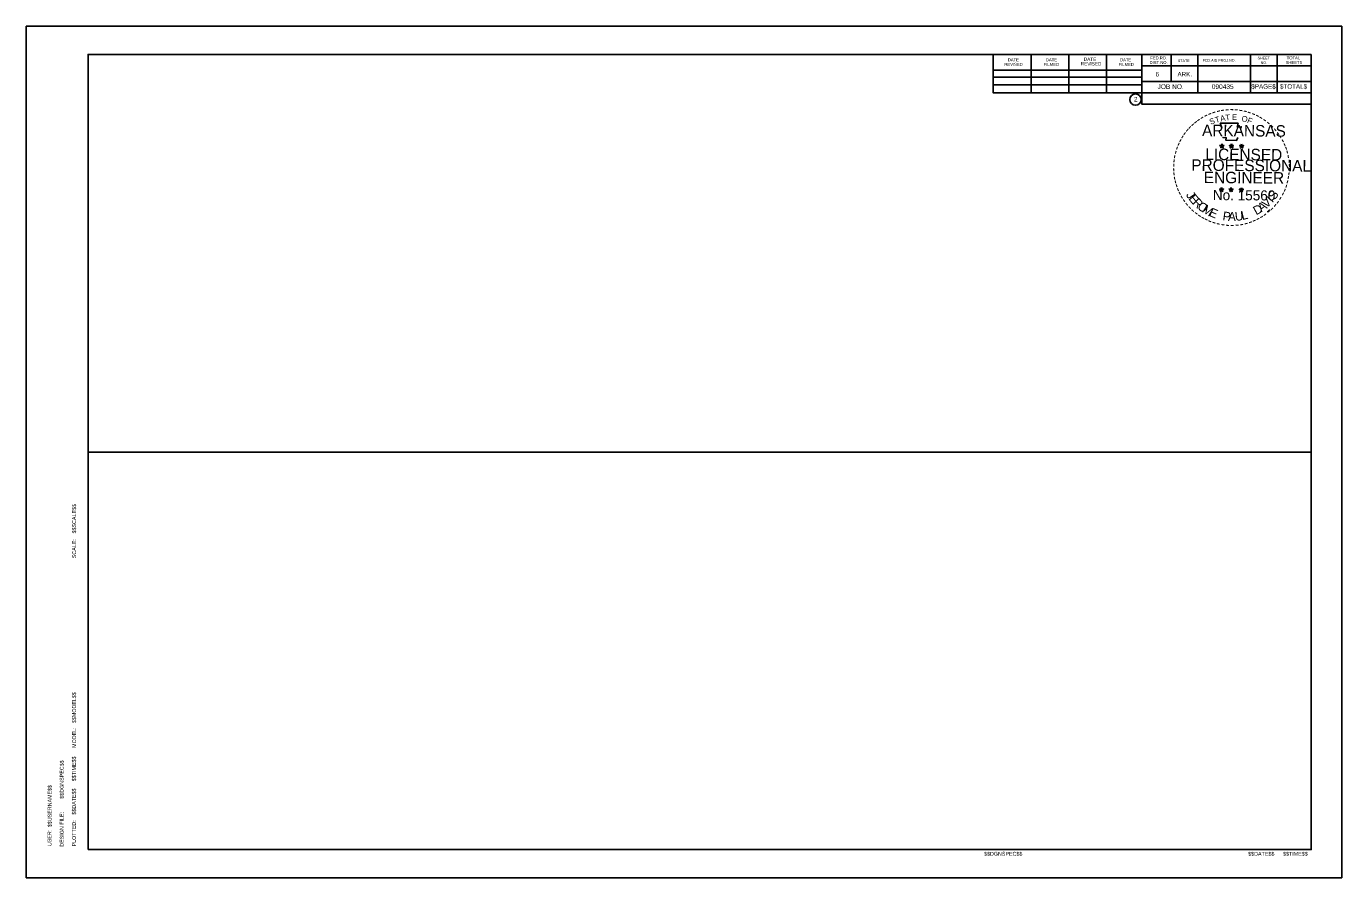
# Model space of a CAD drawing. Extents: x -1.6 to 32.4, y -0.7 to 21.3.
import ezdxf

# ---------------------------------------------------------------- set-up
doc = ezdxf.new("R2010")
doc.units = 0
for name, color, linetype in [('Level 1', 7, 'Continuous'), ('Level 24', 7, 'Continuous'), ('Level 37', 7, 'Continuous'), ('Level 48', 7, 'Continuous'), ('Level 49', 7, 'Continuous'), ('Level 62', 7, 'Continuous'), ('Level 63', 7, 'Continuous')]:
    doc.layers.add(name, color=color, linetype=linetype)

msp = doc.modelspace()

# ---------------------------------------------------------------- linework, layer by layer
at = {"layer": 'Level 1'}
for p, q in [((-0.001, 20.545), (31.617, 20.545)), ((-0.001, -0.001), (-0.001, 20.545)), ((23.391, 19.557), (23.391, 20.545)), ((24.377, 19.557), (24.377, 20.525)), ((25.353, 19.557), (25.353, 20.525)), ((26.321, 19.557), (26.321, 20.525)), ((27.233, 20.545), (27.233, 19.557)), ((27.991, 20.545), (27.991, 19.851)), ((28.685, 20.545), (28.685, 19.557)), ((30.043, 20.545), (30.043, 19.557)), ((30.737, 20.545), (30.737, 19.557)), ((31.617, -0.001), (31.617, 20.545)), ((23.391, 20.143), (27.233, 20.143)), ((31.617, 20.251), (27.233, 20.251)), ((31.617, 20.253), (31.617, 20.253)), ((23.391, 19.957), (27.233, 19.957)), ((23.391, 19.557), (23.391, 19.763)), ((23.391, 19.763), (27.233, 19.763)), ((31.617, 19.851), (27.233, 19.851)), ((27.603, 19.851), (31.617, 19.851)), ((31.617, 19.557), (23.391, 19.557)), ((27.233, 19.557), (27.233, 19.265)), ((27.233, 19.265), (31.617, 19.265)), ((31.617, -0.001), (-0.001, -0.001))]:
    msp.add_line(p, q, dxfattribs=at)
msp.add_circle((27.073, 19.379), 0.147, dxfattribs=at)
at = {"layer": 'Level 24'}
for p, q in [((-0.001, 20.545), (-0.001, -0.001)), ((23.391, 19.557), (23.391, 20.545)), ((26.999, 19.557), (23.391, 19.557)), ((27.233, 19.557), (26.999, 19.557)), ((27.233, 19.265), (27.233, 19.557)), ((27.233, 19.557), (27.233, 19.557)), ((31.617, 19.265), (27.233, 19.265)), ((31.617, -0.001), (31.617, 19.265)), ((-0.001, -0.001), (31.617, -0.001))]:
    msp.add_line(p, q, dxfattribs=at)
msp.add_lwpolyline([(23.391, 20.545), (23.391, 20.545), (23.391, 20.545), (-0.001, 20.545)], dxfattribs=at)
at = {"layer": 'Level 37'}
for p, q in [((-0.002, 10.755), (-0.001, 20.545)), ((-0.001, 20.545), (31.617, 20.545)), ((31.617, 20.545), (31.617, 10.273)), ((-0.001, 10.273), (-0.002, 10.755)), ((-0.002, 10.755), (-0.002, 10.755)), ((-0.002, 0.481), (-0.001, 10.271)), ((-0.002, 0.481), (-0.001, 10.271)), ((31.617, 10.273), (-0.001, 10.273)), ((-0.001, 10.271), (31.617, 10.271)), ((-0.001, 10.271), (31.617, 10.271)), ((31.617, 10.271), (31.617, -0.001)), ((31.617, 10.271), (31.617, -0.001)), ((-0.001, -0.001), (-0.002, 0.481)), ((-0.002, 0.481), (-0.002, 0.481)), ((-0.001, -0.001), (-0.002, 0.481)), ((-0.002, 0.481), (-0.002, 0.481)), ((31.617, -0.001), (-0.001, -0.001)), ((31.617, -0.001), (-0.001, -0.001))]:
    msp.add_line(p, q, dxfattribs=at)
at = {"layer": 'Level 49'}
for p, q in [((29.252, 18.195), (29.306, 18.178)), ((29.252, 18.195), (29.291, 18.193)), ((29.252, 18.195), (29.291, 18.191)), ((29.252, 18.195), (29.287, 18.186)), ((29.252, 18.195), (29.287, 18.18)), ((29.252, 18.195), (29.287, 18.178)), ((29.252, 18.195), (29.287, 18.173)), ((29.274, 18.134), (29.306, 18.178)), ((29.274, 18.134), (29.287, 18.176)), ((29.274, 18.134), (29.291, 18.171)), ((29.274, 18.134), (29.293, 18.169)), ((29.274, 18.134), (29.298, 18.165)), ((29.274, 18.134), (29.306, 18.165)), ((29.274, 18.134), (29.306, 18.162)), ((29.306, 18.235), (29.298, 18.195)), ((29.306, 18.235), (29.298, 18.199)), ((29.306, 18.235), (29.302, 18.199)), ((29.306, 18.178), (29.306, 18.235)), ((29.306, 18.235), (29.315, 18.195)), ((29.306, 18.235), (29.313, 18.199)), ((29.306, 18.235), (29.307, 18.199)), ((29.357, 18.195), (29.306, 18.178)), ((29.337, 18.132), (29.306, 18.178)), ((29.337, 18.132), (29.306, 18.165)), ((29.337, 18.132), (29.306, 18.162)), ((29.357, 18.195), (29.309, 18.191)), ((29.337, 18.132), (29.309, 18.165)), ((29.357, 18.195), (29.315, 18.188)), ((29.357, 18.195), (29.315, 18.184)), ((29.337, 18.132), (29.315, 18.176)), ((29.337, 18.132), (29.315, 18.171)), ((29.337, 18.132), (29.32, 18.178)), ((29.357, 18.195), (29.322, 18.184)), ((29.357, 18.195), (29.328, 18.18)), ((29.357, 18.195), (29.329, 18.178)), ((29.5, 18.193), (29.553, 18.178)), ((29.5, 18.193), (29.539, 18.191)), ((29.5, 18.193), (29.539, 18.188)), ((29.5, 18.193), (29.539, 18.186)), ((29.5, 18.193), (29.537, 18.178)), ((29.5, 18.193), (29.537, 18.176)), ((29.5, 18.193), (29.537, 18.171)), ((29.522, 18.132), (29.553, 18.178)), ((29.522, 18.132), (29.539, 18.173)), ((29.522, 18.132), (29.539, 18.171)), ((29.522, 18.132), (29.541, 18.169)), ((29.522, 18.132), (29.546, 18.164)), ((29.522, 18.132), (29.553, 18.164)), ((29.522, 18.132), (29.553, 18.162)), ((29.553, 18.232), (29.546, 18.193)), ((29.553, 18.232), (29.546, 18.195)), ((29.553, 18.232), (29.548, 18.195)), ((29.553, 18.178), (29.553, 18.232)), ((29.553, 18.232), (29.563, 18.193)), ((29.553, 18.232), (29.561, 18.195)), ((29.553, 18.232), (29.555, 18.195)), ((29.605, 18.193), (29.553, 18.178)), ((29.585, 18.132), (29.553, 18.178)), ((29.585, 18.132), (29.553, 18.164)), ((29.585, 18.132), (29.553, 18.162)), ((29.605, 18.193), (29.559, 18.191)), ((29.585, 18.132), (29.559, 18.164)), ((29.605, 18.193), (29.563, 18.186)), ((29.605, 18.193), (29.563, 18.184)), ((29.585, 18.132), (29.563, 18.176)), ((29.585, 18.132), (29.563, 18.169)), ((29.585, 18.132), (29.568, 18.176)), ((29.605, 18.193), (29.57, 18.18)), ((29.605, 18.193), (29.575, 18.178)), ((29.605, 18.193), (29.577, 18.176)), ((29.763, 18.191), (29.816, 18.173)), ((29.763, 18.191), (29.805, 18.186)), ((29.763, 18.191), (29.801, 18.184)), ((29.763, 18.191), (29.801, 18.18)), ((29.763, 18.191), (29.799, 18.176)), ((29.763, 18.191), (29.799, 18.171)), ((29.763, 18.191), (29.799, 18.171)), ((29.783, 18.131), (29.816, 18.173)), ((29.783, 18.131), (29.801, 18.171)), ((29.783, 18.131), (29.805, 18.165)), ((29.783, 18.131), (29.805, 18.164)), ((29.783, 18.131), (29.816, 18.164)), ((29.783, 18.131), (29.812, 18.162)), ((29.783, 18.131), (29.82, 18.156)), ((29.816, 18.228), (29.807, 18.193)), ((29.816, 18.228), (29.812, 18.191)), ((29.816, 18.228), (29.812, 18.191)), ((29.816, 18.173), (29.816, 18.228)), ((29.816, 18.228), (29.827, 18.191)), ((29.816, 18.228), (29.823, 18.191)), ((29.816, 18.228), (29.82, 18.191)), ((29.867, 18.191), (29.816, 18.173)), ((29.845, 18.131), (29.816, 18.173)), ((29.845, 18.131), (29.816, 18.164)), ((29.845, 18.131), (29.816, 18.156)), ((29.867, 18.191), (29.821, 18.186)), ((29.845, 18.131), (29.821, 18.162)), ((29.867, 18.191), (29.827, 18.184)), ((29.867, 18.191), (29.827, 18.178)), ((29.845, 18.131), (29.827, 18.171)), ((29.845, 18.131), (29.827, 18.165)), ((29.845, 18.131), (29.831, 18.171)), ((29.867, 18.191), (29.834, 18.176)), ((29.867, 18.191), (29.836, 18.176)), ((29.867, 18.191), (29.842, 18.173)), ((29.245, 17.068), (29.298, 17.051)), ((29.245, 17.068), (29.284, 17.066)), ((29.245, 17.068), (29.282, 17.06)), ((29.245, 17.068), (29.282, 17.06)), ((29.245, 17.068), (29.282, 17.053)), ((29.245, 17.068), (29.282, 17.051)), ((29.245, 17.068), (29.282, 17.049)), ((29.263, 17.011), (29.298, 17.051)), ((29.263, 17.011), (29.282, 17.051)), ((29.263, 17.011), (29.284, 17.044)), ((29.263, 17.011), (29.285, 17.044)), ((29.263, 17.011), (29.298, 17.042)), ((29.263, 17.011), (29.291, 17.038)), ((29.263, 17.011), (29.298, 17.037)), ((29.298, 17.108), (29.287, 17.071)), ((29.298, 17.108), (29.291, 17.068)), ((29.298, 17.108), (29.293, 17.068)), ((29.328, 17.007), (29.295, 17.037)), ((29.298, 17.051), (29.298, 17.108)), ((29.298, 17.108), (29.306, 17.068)), ((29.298, 17.108), (29.306, 17.068)), ((29.298, 17.108), (29.298, 17.068)), ((29.35, 17.068), (29.298, 17.051)), ((29.328, 17.007), (29.298, 17.051)), ((29.328, 17.007), (29.298, 17.038)), ((29.328, 17.007), (29.3, 17.038)), ((29.35, 17.068), (29.302, 17.066)), ((29.35, 17.068), (29.306, 17.06)), ((29.35, 17.068), (29.306, 17.059)), ((29.328, 17.007), (29.306, 17.051)), ((29.328, 17.007), (29.306, 17.044)), ((29.35, 17.068), (29.313, 17.057)), ((29.328, 17.007), (29.313, 17.051)), ((29.35, 17.068), (29.317, 17.053)), ((29.35, 17.068), (29.32, 17.051)), ((29.493, 17.068), (29.546, 17.051)), ((29.493, 17.068), (29.531, 17.064)), ((29.493, 17.068), (29.531, 17.06)), ((29.493, 17.068), (29.531, 17.059)), ((29.493, 17.068), (29.53, 17.053)), ((29.493, 17.068), (29.53, 17.049)), ((29.493, 17.068), (29.53, 17.046)), ((29.511, 17.007), (29.546, 17.051)), ((29.511, 17.007), (29.531, 17.049)), ((29.511, 17.007), (29.531, 17.042)), ((29.511, 17.007), (29.533, 17.042)), ((29.511, 17.007), (29.539, 17.038)), ((29.511, 17.007), (29.546, 17.038)), ((29.511, 17.007), (29.546, 17.035)), ((29.546, 17.104), (29.537, 17.068)), ((29.546, 17.104), (29.539, 17.068)), ((29.546, 17.104), (29.541, 17.068)), ((29.575, 17.007), (29.544, 17.035)), ((29.546, 17.051), (29.546, 17.104)), ((29.546, 17.104), (29.553, 17.066)), ((29.546, 17.104), (29.553, 17.066)), ((29.546, 17.104), (29.546, 17.068)), ((29.596, 17.066), (29.546, 17.051)), ((29.575, 17.007), (29.546, 17.051)), ((29.575, 17.007), (29.546, 17.038)), ((29.575, 17.007), (29.548, 17.038)), ((29.596, 17.066), (29.552, 17.066)), ((29.596, 17.066), (29.553, 17.059)), ((29.596, 17.066), (29.553, 17.059)), ((29.575, 17.007), (29.553, 17.049)), ((29.575, 17.007), (29.553, 17.044)), ((29.596, 17.066), (29.561, 17.053)), ((29.575, 17.007), (29.561, 17.049)), ((29.596, 17.066), (29.566, 17.051)), ((29.596, 17.066), (29.568, 17.049)), ((29.755, 17.064), (29.809, 17.046)), ((29.755, 17.064), (29.794, 17.06)), ((29.755, 17.064), (29.794, 17.057)), ((29.755, 17.064), (29.792, 17.053)), ((29.755, 17.064), (29.792, 17.049)), ((29.755, 17.064), (29.79, 17.046)), ((29.755, 17.064), (29.79, 17.042)), ((29.775, 17.003), (29.809, 17.046)), ((29.775, 17.003), (29.792, 17.046)), ((29.775, 17.003), (29.794, 17.038)), ((29.775, 17.003), (29.798, 17.038)), ((29.775, 17.003), (29.801, 17.035)), ((29.775, 17.003), (29.807, 17.035)), ((29.775, 17.003), (29.809, 17.031)), ((29.809, 17.103), (29.799, 17.064)), ((29.809, 17.103), (29.801, 17.064)), ((29.809, 17.103), (29.805, 17.064)), ((29.838, 17.003), (29.807, 17.035)), ((29.838, 17.003), (29.807, 17.031)), ((29.809, 17.046), (29.809, 17.103)), ((29.809, 17.103), (29.816, 17.064)), ((29.809, 17.103), (29.816, 17.064)), ((29.809, 17.103), (29.809, 17.064)), ((29.86, 17.064), (29.809, 17.046)), ((29.838, 17.003), (29.809, 17.046)), ((29.838, 17.003), (29.812, 17.035)), ((29.86, 17.064), (29.814, 17.06)), ((29.86, 17.064), (29.816, 17.057)), ((29.86, 17.064), (29.816, 17.053)), ((29.838, 17.003), (29.816, 17.038)), ((29.838, 17.003), (29.82, 17.046)), ((29.838, 17.003), (29.821, 17.046)), ((29.86, 17.064), (29.827, 17.051)), ((29.86, 17.064), (29.829, 17.046)), ((29.86, 17.064), (29.831, 17.046))]:
    msp.add_line(p, q, dxfattribs=at)
for points in [[(29.263, 18.773), (29.3, 18.648)], [(29.785, 18.632), (29.807, 18.676), (29.702, 18.67), (29.726, 18.769), (29.263, 18.773)], [(29.335, 18.411), (29.335, 18.397), (29.418, 18.395), (29.41, 18.327), (29.687, 18.325), (29.717, 18.402)], [(29.306, 18.235), (29.337, 18.132), (29.252, 18.195), (29.357, 18.195), (29.274, 18.134), (29.306, 18.235)], [(29.553, 18.232), (29.585, 18.132), (29.5, 18.193), (29.605, 18.193), (29.522, 18.132), (29.553, 18.232)], [(29.816, 18.228), (29.845, 18.131), (29.763, 18.191), (29.867, 18.191), (29.783, 18.131), (29.816, 18.228)], [(29.298, 17.108), (29.328, 17.007), (29.245, 17.068), (29.35, 17.068), (29.263, 17.011), (29.298, 17.108)], [(29.546, 17.104), (29.575, 17.007), (29.493, 17.068), (29.596, 17.066), (29.511, 17.007), (29.546, 17.104)], [(29.809, 17.103), (29.838, 17.003), (29.755, 17.064), (29.86, 17.064), (29.775, 17.003), (29.809, 17.103)], [(30.497, 16.467), (30.49, 16.491), (30.534, 16.528)], [(30.53, 16.534), (30.537, 16.512), (30.493, 16.473)], [(30.537, 16.515), (30.493, 16.477)], [(30.537, 16.512), (30.495, 16.475)]]:
    msp.add_lwpolyline(points, dxfattribs=at)
for centre, radius in [((29.306, 18.177), 0.0256), ((29.306, 18.177), 0.0232), ((29.306, 18.177), 0.0215), ((29.306, 18.177), 0.0197), ((29.306, 18.177), 0.0172), ((29.306, 18.177), 0.016), ((29.306, 18.177), 0.0147), ((29.306, 18.177), 0.0127), ((29.306, 18.177), 0.0111), ((29.306, 18.177), 0.00924), ((29.306, 18.177), 0.00737), ((29.306, 18.177), 0.0055), ((29.306, 18.177), 0.00441), ((29.306, 18.177), 0.00214), ((29.555, 18.176), 0.0256), ((29.555, 18.176), 0.0232), ((29.555, 18.176), 0.0215), ((29.555, 18.176), 0.0197), ((29.555, 18.176), 0.0172), ((29.555, 18.176), 0.016), ((29.555, 18.176), 0.0147), ((29.555, 18.176), 0.0127), ((29.555, 18.176), 0.0111), ((29.555, 18.176), 0.00924), ((29.555, 18.176), 0.00737), ((29.555, 18.176), 0.0055), ((29.555, 18.176), 0.00441), ((29.555, 18.176), 0.00214), ((29.817, 18.172), 0.0256), ((29.817, 18.172), 0.0232), ((29.817, 18.172), 0.0215), ((29.817, 18.172), 0.0197), ((29.817, 18.172), 0.0172), ((29.817, 18.172), 0.016), ((29.817, 18.172), 0.0147), ((29.817, 18.172), 0.0127), ((29.817, 18.172), 0.0111), ((29.817, 18.172), 0.00924), ((29.817, 18.172), 0.00737), ((29.817, 18.172), 0.0055), ((29.817, 18.172), 0.00441), ((29.817, 18.172), 0.00214), ((29.298, 17.051), 0.0256), ((29.298, 17.051), 0.0232), ((29.298, 17.051), 0.0215), ((29.298, 17.051), 0.0197), ((29.298, 17.051), 0.0172), ((29.298, 17.051), 0.016), ((29.298, 17.051), 0.0147), ((29.298, 17.051), 0.0127), ((29.298, 17.051), 0.0111), ((29.298, 17.051), 0.00924), ((29.298, 17.051), 0.00737), ((29.298, 17.051), 0.0055), ((29.298, 17.051), 0.00441), ((29.298, 17.051), 0.00214), ((29.546, 17.049), 0.0256), ((29.546, 17.049), 0.0232), ((29.546, 17.049), 0.0215), ((29.546, 17.049), 0.0197), ((29.546, 17.049), 0.0172), ((29.546, 17.049), 0.016), ((29.546, 17.049), 0.0147), ((29.546, 17.049), 0.0127), ((29.546, 17.049), 0.0111), ((29.546, 17.049), 0.00924), ((29.546, 17.049), 0.00737), ((29.546, 17.049), 0.0055), ((29.546, 17.049), 0.00441), ((29.546, 17.049), 0.00214), ((29.809, 17.046), 0.0256), ((29.809, 17.046), 0.0232), ((29.809, 17.046), 0.0215), ((29.809, 17.046), 0.0197), ((29.809, 17.046), 0.0172), ((29.809, 17.046), 0.016), ((29.809, 17.046), 0.0147), ((29.809, 17.046), 0.0127), ((29.809, 17.046), 0.0111), ((29.809, 17.046), 0.00924), ((29.809, 17.046), 0.00737), ((29.809, 17.046), 0.0055), ((29.809, 17.046), 0.00441), ((29.809, 17.046), 0.00214)]:
    msp.add_circle(centre, radius, dxfattribs=at)
at = {"layer": 'Level 62'}
msp.add_lwpolyline([(-0.001, -0.001), (31.617, -0.001), (31.617, 19.265), (27.233, 19.265), (27.233, 19.557), (27.233, 19.557), (26.999, 19.557), (23.391, 19.557), (23.391, 20.545), (23.391, 20.545), (23.391, 20.545), (-0.001, 20.545)], close=True, dxfattribs=at)
at = {"layer": 'Level 63'}
msp.add_lwpolyline([(-1.598, 21.273), (32.402, 21.273), (32.402, -0.727), (-1.598, -0.727)], close=True, dxfattribs=at)

# ---------------------------------------------------------------- texts
at = {"layer": 'Level 1'}
for s, height, p in [('DATE', 0.0782, (23.771, 20.369)), ('DATE', 0.0782, (24.757, 20.369)), ('DATE', 0.0879, (25.735, 20.379)), ('DATE', 0.0782, (26.673, 20.369)), ('FED.RD.', 0.0782, (27.455, 20.417)), ('STATE', 0.0684, (28.167, 20.349)), ('FED.AID PROJ.NO.', 0.0684, (28.813, 20.359)), ('SHEET', 0.0684, (30.229, 20.417)), ('TOTAL', 0.0782, (30.981, 20.417)), ('REVISED', 0.0782, (23.683, 20.251)), ('FILMED', 0.0782, (24.699, 20.251)), ('REVISED', 0.0879, (25.657, 20.261)), ('FILMED', 0.0782, (26.633, 20.251)), ('DIST.NO.', 0.0782, (27.435, 20.299)), ('6', 0.117, (27.591, 19.977)), ('ARK.', 0.1172, (28.157, 19.977)), ('NO.', 0.0684, (30.307, 20.299)), ('SHEETS', 0.0782, (30.953, 20.299)), ('JOB NO.', 0.1224, (27.643, 19.653)), ('090435', 0.1224, (29.045, 19.653)), ('$PAGE$', 0.1172, (30.067, 19.66)), ('$TOTAL$', 0.1172, (30.806, 19.66)), ('2', 0.117, (27.034, 19.329))]:
    msp.add_text(s, height=height, dxfattribs=at).set_placement(p)
for s, p in [('$$SCALE$$', (-0.313, 8.169)), ('SCALE:', (-0.313, 7.528)), ('$$MODEL$$', (-0.313, 3.269)), ('MODEL:', (-0.313, 2.628)), ('$$TIME$$', (-0.316, 1.767)), ('$$DGNSPEC$$', (-0.632, 1.314)), ('$$USERNAME$$', (-0.944, 0.58)), ('$$DATE$$', (-0.316, 0.903)), ('DESIGN FILE:', (-0.632, 0.073)), ('PLOTTED:', (-0.316, 0.081)), ('USER:', (-0.948, 0.089))]:
    msp.add_text(s, height=0.1, rotation=90, dxfattribs=at).set_placement(p)
at = {"layer": 'Level 48'}
for s, p in [('$$DGNSPEC$$', (23.157, -0.159)), ('$$DATE$$', (29.986, -0.159)), ('$$TIME$$', (30.887, -0.159))]:
    msp.add_text(s, height=0.1, dxfattribs=at).set_placement(p)
at = {"layer": 'Level 49'}
for s, height, rotation, p in [('-', 0.238, 18.7785, (29.076, 18.944)), ('-', 0.238, 13.2326, (29.188, 18.979)), ('-', 0.238, 9.8217, (29.287, 19.003)), ('-', 0.238, 5.4992, (29.397, 19.017)), ('-', 0.238, 359.7886, (29.511, 19.028)), ('-', 0.238, 357.3454, (29.621, 19.025)), ('-', 0.238, 351.7641, (29.73, 19.015)), ('-', 0.238, 346.8073, (29.838, 18.999)), ('-', 0.238, 341.9386, (29.932, 18.973)), ('-', 0.238, 42.5646, (28.575, 18.628)), ('-', 0.238, 38.5531, (28.641, 18.689)), ('-', 0.238, 35.8341, (28.711, 18.746)), ('-', 0.238, 33.666, (28.797, 18.804)), ('ARKANSAS', 0.2974, 359.6024, (28.792, 18.435)), ('-', 0.238, 28.3942, (28.887, 18.858)), ('-', 0.238, 23.9096, (28.981, 18.903)), ('S', 0.149, 21.1964, (29.016, 18.727)), ('T', 0.149, 16.006, (29.151, 18.777)), ('A', 0.149, 10.8156, (29.276, 18.813)), ('T', 0.149, 5.6252, (29.403, 18.837)), ('E', 0.149, 0.4347, (29.566, 18.852)), ('O', 0.149, 350.0539, (29.805, 18.821)), ('F', 0.149, 339.6731, (29.946, 18.784)), ('-', 0.238, 337.4575, (30.04, 18.94)), ('-', 0.238, 333.7235, (30.135, 18.902)), ('-', 0.238, 329.2433, (30.22, 18.858)), ('-', 0.238, 325.4651, (30.315, 18.801)), ('-', 0.238, 320.1321, (30.405, 18.738)), ('-', 0.238, 315.181, (30.495, 18.665)), ('-', 0.238, 62.4738, (28.29, 18.232)), ('-', 0.238, 57.673, (28.336, 18.322)), ('-', 0.238, 53.8349, (28.384, 18.402)), ('-', 0.238, 50.2166, (28.446, 18.487)), ('-', 0.238, 48.0254, (28.507, 18.558)), ('-', 0.238, 309.4821, (30.578, 18.582)), ('-', 0.238, 306.2546, (30.653, 18.492)), ('-', 0.208, 303.2777, (30.726, 18.406)), ('-', 0.238, 75.0634, (28.188, 17.942)), ('-', 0.238, 71.9969, (28.217, 18.048)), ('-', 0.238, 67.3767, (28.252, 18.142)), ('LICENSED', 0.2974, 359.6024, (28.875, 17.819)), ('-', 0.238, 299.2708, (30.772, 18.316)), ('-', 0.238, 294.2652, (30.82, 18.224)), ('-', 0.238, 290.1752, (30.86, 18.142)), ('-', 0.238, 284.7257, (30.892, 18.054)), ('-', 0.238, 88.6646, (28.151, 17.629)), ('-', 0.238, 84.7887, (28.155, 17.734)), ('-', 0.238, 80.8037, (28.166, 17.837)), ('PROFESSIONAL', 0.29745, 359.6024, (28.514, 17.54)), ('-', 0.238, 280.1517, (30.921, 17.942)), ('-', 0.238, 276.1986, (30.947, 17.828)), ('-', 0.238, 273.9325, (30.954, 17.719)), ('-', 0.238, 93.7983, (28.155, 17.521)), ('-', 0.238, 98.5503, (28.166, 17.42)), ('-', 0.238, 101.3173, (28.182, 17.312)), ('ENGINEER', 0.2974, 359.6024, (28.836, 17.222)), ('-', 0.238, 260.5977, (30.941, 17.431)), ('-', 0.238, 263.1196, (30.954, 17.528)), ('-', 0.238, 269.5431, (30.958, 17.628)), ('-', 0.238, 105.0602, (28.208, 17.224)), ('-', 0.238, 108.6898, (28.239, 17.132)), ('-', 0.238, 113.6667, (28.276, 17.04)), ('No. 15560', 0.2617, 359.6024, (29.071, 16.782)), ('S', 0.229, 53.5227, (30.666, 16.768)), ('-', 0.238, 247.4911, (30.866, 17.121)), ('-', 0.238, 252.4705, (30.899, 17.222)), ('-', 0.238, 255.365, (30.925, 17.33)), ('-', 0.238, 115.3313, (28.322, 16.948)), ('-', 0.238, 120.0495, (28.373, 16.86)), ('-', 0.238, 125.4958, (28.434, 16.778)), ('-', 0.238, 130.3205, (28.5, 16.695)), ('J', 0.229, 303.9209, (28.367, 16.913)), ('E', 0.229, 308.618, (28.431, 16.817)), ('R', 0.229, 314.7784, (28.527, 16.7)), ('O', 0.229, 321.6761, (28.649, 16.582)), ('M', 0.229, 328.1357, (28.775, 16.486)), ('A', 0.229, 34.8903, (30.326, 16.463)), ('V', 0.229, 41.4844, (30.457, 16.558)), ('I', 0.229, 49.9999, (30.609, 16.702)), ('-', 0.238, 233.4476, (30.638, 16.741)), ('-', 0.238, 233.4476, (30.708, 16.822)), ('-', 0.238, 238.6736, (30.765, 16.919)), ('-', 0.238, 244.2221, (30.824, 17.029)), ('-', 0.238, 133.8262, (28.577, 16.614)), ('-', 0.238, 138.5362, (28.652, 16.545)), ('-', 0.238, 144.2487, (28.738, 16.484)), ('-', 0.238, 147.6922, (28.819, 16.427)), ('-', 0.238, 151.1728, (28.904, 16.379)), ('E', 0.229, 336.4966, (28.953, 16.383)), ('P', 0.229, 351.9783, (29.314, 16.265)), ('A', 0.229, 357.9896, (29.461, 16.246)), ('U', 0.229, 5.7635, (29.652, 16.244)), ('L', 0.229, 13.0992, (29.831, 16.266)), ('D', 0.229, 28.5809, (30.191, 16.387)), ('-', 0.238, 206.9592, (30.245, 16.401)), ('-', 0.238, 211.8515, (30.328, 16.453)), ('-', 0.238, 215.3387, (30.407, 16.51)), ('-', 0.238, 225.3677, (30.569, 16.655)), ('-', 0.238, 154.2026, (28.984, 16.341)), ('-', 0.238, 158.1636, (29.076, 16.3)), ('-', 0.238, 162.4007, (29.179, 16.269)), ('-', 0.238, 167.1579, (29.284, 16.245)), ('-', 0.238, 172.7179, (29.397, 16.229)), ('-', 0.238, 176.1207, (29.509, 16.218)), ('-', 0.238, 181.1942, (29.619, 16.221)), ('-', 0.238, 185.4191, (29.741, 16.231)), ('-', 0.238, 190.8882, (29.851, 16.249)), ('-', 0.238, 195.0767, (29.959, 16.278)), ('-', 0.238, 200.3208, (30.06, 16.315)), ('-', 0.238, 203.854, (30.152, 16.355))]:
    msp.add_text(s, height=height, rotation=rotation, dxfattribs=at).set_placement(p)

doc.saveas('drawing.dxf')
